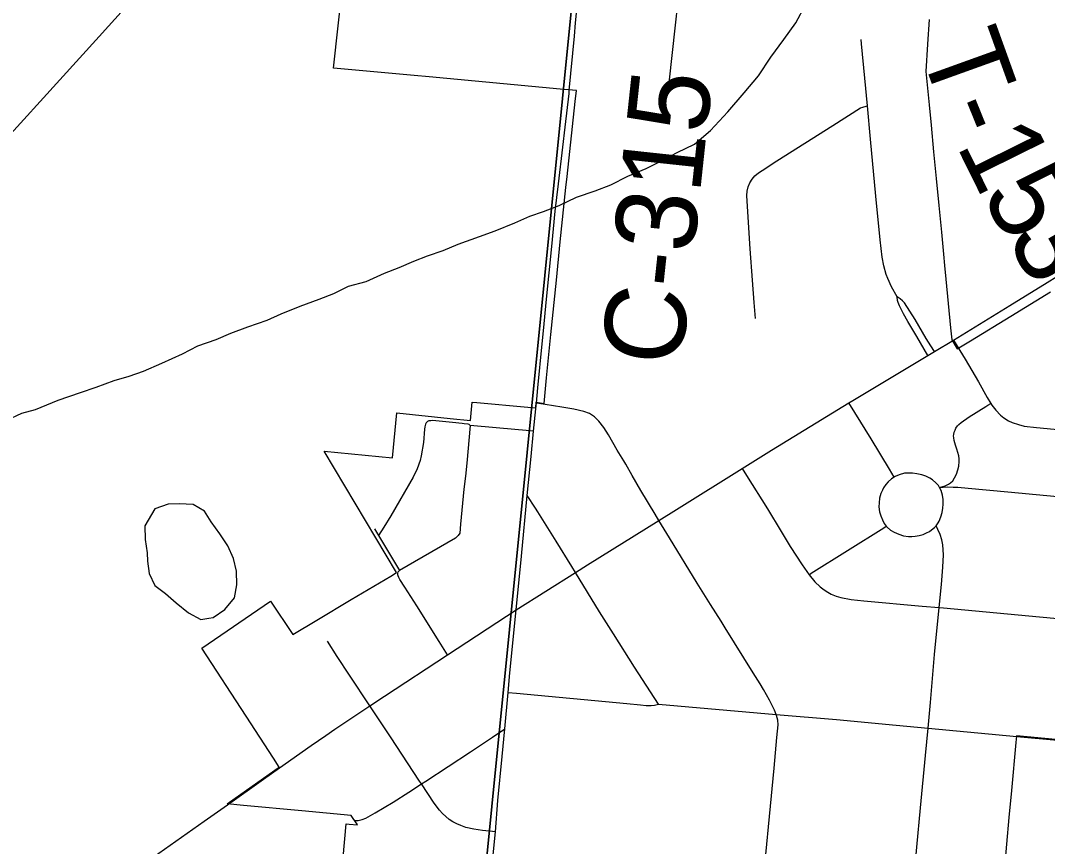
# Model space of a CAD drawing. Extents: x 0 to 1134, y 0 to 440.
# Drawn here: x 840.146 to 840.868, y 359.679 to 360.26 of the extents above; entities that cross this region are included whole.
import ezdxf

# ---------------------------------------------------------------- set-up
doc = ezdxf.new("R2010")
doc.units = 0
for name, color, linetype in [('GM_X_City_Street', 7, 'Continuous'), ('GM_X_Corporation', 7, 'Continuous'), ('GM_X_County_Road', 7, 'Continuous'), ('GM_X_County_Road_Text', 7, 'Continuous'), ('GM_X_Minor_Lake', 7, 'Continuous'), ('GM_X_Minor_River', 7, 'Continuous'), ('GM_X_Rail_Line', 7, 'Continuous'), ('GM_X_Section', 7, 'Continuous'), ('GM_X_Township_Road', 7, 'Continuous'), ('GM_X_Township_Road_Text', 7, 'Continuous')]:
    doc.layers.add(name, color=color, linetype=linetype)

msp = doc.modelspace()

# ---------------------------------------------------------------- linework, layer by layer
at = {"layer": 'GM_X_City_Street'}
for p, q in [((840.3949, 359.90277), (840.39781, 359.89807)), ((840.39781, 359.89807), (840.41256, 359.87346))]:
    msp.add_line(p, q, dxfattribs=at)
for points in [[(840.60156, 360.20947), (840.60228, 360.21871), (840.61255, 360.31077), (840.61317, 360.31691), (840.61324, 360.31949), (840.61302, 360.32134), (840.61271, 360.32289), (840.61213, 360.32471), (840.61181, 360.32541), (840.61122, 360.32624), (840.61051, 360.32689), (840.60976, 360.32745), (840.6084, 360.32821)], [(840.76245, 360.06595), (840.75853, 360.07314), (840.75583, 360.07879), (840.75474, 360.08173), (840.75308, 360.08777), (840.75197, 360.09389), (840.75048, 360.10621), (840.74758, 360.13693), (840.74385, 360.17686), (840.74161, 360.20026), (840.73973, 360.21989), (840.7375, 360.24399), (840.73726, 360.24699)], [(840.66282, 360.0507), (840.66186, 360.06191), (840.66066, 360.07778), (840.65911, 360.09976), (840.65784, 360.11837), (840.65686, 360.13721), (840.65704, 360.14031), (840.6577, 360.14333), (840.65888, 360.14621), (840.66047, 360.14887), (840.6625, 360.15121), (840.66492, 360.15317), (840.66748, 360.15493), (840.67787, 360.16175), (840.71732, 360.18655), (840.73667, 360.19893), (840.73842, 360.19949), (840.74073, 360.20005), (840.74161, 360.20026)], [(840.78871, 360.02752), (840.78623, 360.03149), (840.78299, 360.03668), (840.77504, 360.05002), (840.76754, 360.06169), (840.76635, 360.0632), (840.76468, 360.06454), (840.76245, 360.06595)], [(840.78416, 360.02479), (840.78155, 360.02928), (840.7764, 360.03811), (840.77006, 360.04855), (840.76703, 360.05394), (840.7642, 360.05967), (840.76322, 360.06194), (840.76279, 360.06349), (840.76245, 360.06595)], [(840.80205, 360.03551), (840.81037, 360.02212), (840.81962, 360.00617), (840.82571, 359.99509), (840.82833, 359.99104), (840.82911, 359.98983), (840.83177, 359.9862), (840.83515, 359.98282), (840.83758, 359.98088), (840.84084, 359.97883), (840.84326, 359.97762), (840.84773, 359.97617), (840.85184, 359.97508), (840.86042, 359.97397), (840.9175, 359.96867), (840.91973, 359.96846)], [(840.59481, 359.90874), (840.5922, 359.91315), (840.58234, 359.92978), (840.57603, 359.9403), (840.57157, 359.94817), (840.5703, 359.9506), (840.56557, 359.95812), (840.55946, 359.96892), (840.55622, 359.97414), (840.55262, 359.97863), (840.54974, 359.98151), (840.54614, 359.98385), (840.54219, 359.98529), (840.53517, 359.9869), (840.52672, 359.98835), (840.51506, 359.99028), (840.50886, 359.99129)], [(840.76049, 359.9392), (840.75707, 359.94482), (840.74413, 359.96603), (840.73268, 359.98469), (840.72858, 359.99138)], [(840.79231, 359.93183), (840.79614, 359.93304), (840.79855, 359.93415), (840.80006, 359.93526), (840.80157, 359.93667), (840.80288, 359.93871), (840.8042, 359.94136), (840.80526, 359.94427), (840.80592, 359.94691), (840.80618, 359.95008), (840.806, 359.95205), (840.80579, 359.95405), (840.80433, 359.9589), (840.80354, 359.96158), (840.803, 359.96335), (840.80248, 359.96503), (840.80223, 359.96669), (840.80218, 359.96821), (840.80229, 359.96925), (840.80265, 359.97077), (840.80318, 359.97213), (840.80385, 359.97364), (840.80495, 359.97522), (840.80592, 359.97626), (840.80746, 359.97762), (840.81316, 359.98147), (840.82482, 359.98883), (840.82628, 359.98974), (840.82833, 359.99104)], [(840.46229, 359.97558), (840.46143, 359.97618), (840.4608, 359.97641), (840.45804, 359.97671), (840.45657, 359.97687), (840.44988, 359.97755), (840.43582, 359.9789), (840.4345, 359.97886), (840.43313, 359.97869), (840.43229, 359.97831), (840.43177, 359.97787), (840.43127, 359.97734), (840.43075, 359.97644), (840.43047, 359.97552), (840.43034, 359.97443), (840.43021, 359.97281), (840.42935, 359.96342), (840.42785, 359.95404), (840.42704, 359.95094), (840.42486, 359.94494), (840.42212, 359.93921), (840.40638, 359.91196), (840.40142, 359.90392), (840.39781, 359.89807)], [(840.46229, 359.97558), (840.45986, 359.94902), (840.45885, 359.93987), (840.45788, 359.9307), (840.45543, 359.90606), (840.45495, 359.89969)], [(840.50683, 359.97149), (840.50413, 359.97175), (840.48056, 359.97394), (840.46229, 359.97558)], [(840.65338, 359.9453), (840.65647, 359.94037), (840.67123, 359.91688), (840.68082, 359.90097), (840.6873, 359.89045), (840.69569, 359.87744), (840.7005, 359.87053), (840.7045, 359.86554), (840.70831, 359.86197), (840.71105, 359.85994), (840.71367, 359.85815), (840.71605, 359.85672), (840.71968, 359.85542), (840.72296, 359.85458), (840.73011, 359.85315), (840.73905, 359.85207), (840.77997, 359.84842), (840.79202, 359.84738), (840.79507, 359.84711), (840.9327, 359.83422)], [(840.78985, 359.90496), (840.79133, 359.90706), (840.79197, 359.90807), (840.79322, 359.91122), (840.79417, 359.91429), (840.79465, 359.91725), (840.79494, 359.92022), (840.79494, 359.92347), (840.79438, 359.92646), (840.79342, 359.92982), (840.79231, 359.93183), (840.79144, 359.93327), (840.78962, 359.93519), (840.78728, 359.93715), (840.78537, 359.93839), (840.78269, 359.93974), (840.77992, 359.94069), (840.77628, 359.94155), (840.77331, 359.94194), (840.77064, 359.94203), (840.76757, 359.94184), (840.76387, 359.94089), (840.76107, 359.93959), (840.76049, 359.9392), (840.75853, 359.93785), (840.75622, 359.93582), (840.75456, 359.9339), (840.75288, 359.93154), (840.75208, 359.92997), (840.75093, 359.92768), (840.75016, 359.92443), (840.74988, 359.92118), (840.74968, 359.91821), (840.75016, 359.91486), (840.75103, 359.91199), (840.75208, 359.90921), (840.75342, 359.90644), (840.75483, 359.90462), (840.75542, 359.90386), (840.75782, 359.90185), (840.7604, 359.90041), (840.76375, 359.89897), (840.767, 359.89792), (840.77035, 359.89745), (840.77284, 359.89745), (840.77523, 359.89754), (840.77801, 359.89802), (840.78088, 359.89888), (840.78317, 359.89993), (840.78518, 359.90099), (840.78662, 359.90204), (840.78872, 359.90376), (840.78985, 359.90496)], [(840.79231, 359.93183), (840.79765, 359.93234), (840.80197, 359.93214), (840.8052, 359.93199), (840.8123, 359.93134), (840.84022, 359.92871), (840.91502, 359.92169), (841.01067, 359.91272), (841.01674, 359.91212), (841.0589, 359.908), (841.07221, 359.90664), (841.08044, 359.90589), (841.13596, 359.90053), (841.13828, 359.9003)], [(840.53625, 359.87214), (840.53377, 359.87618), (840.52273, 359.89418), (840.50982, 359.91469), (840.50819, 359.91723), (840.50237, 359.92628)], [(840.66765, 359.64703), (840.67261, 359.70051), (840.67603, 359.73451), (840.67783, 359.7561), (840.67877, 359.76497), (840.67857, 359.76824), (840.67771, 359.7714), (840.6774, 359.77217), (840.67621, 359.77517), (840.67279, 359.78218), (840.66848, 359.78974), (840.66615, 359.79364), (840.66125, 359.80157), (840.64164, 359.83325), (840.63872, 359.83786), (840.63118, 359.84961), (840.62182, 359.8646), (840.60242, 359.89641), (840.59481, 359.90874)], [(840.45495, 359.89969), (840.45381, 359.89803), (840.45183, 359.89616), (840.41256, 359.87346)], [(840.7005, 359.87053), (840.70205, 359.8715), (840.75318, 359.90359), (840.75483, 359.90462)], [(840.75627, 359.46433), (840.75647, 359.46636), (840.76335, 359.5367), (840.76408, 359.5446), (840.77149, 359.62532), (840.77375, 359.64996), (840.77643, 359.67877), (840.77886, 359.70662), (840.78238, 359.74321), (840.78427, 359.76261), (840.78599, 359.78071), (840.7888, 359.81428), (840.79202, 359.84738), (840.79358, 359.86351), (840.79461, 359.87589), (840.79499, 359.88461), (840.79465, 359.89146), (840.79396, 359.89493), (840.79265, 359.89887), (840.79105, 359.90234), (840.78985, 359.90496)], [(840.44637, 359.81411), (840.44287, 359.81966), (840.44043, 359.82352), (840.4246, 359.84863), (840.4163, 359.86171), (840.41283, 359.86719), (840.41201, 359.86866), (840.41156, 359.86966), (840.41136, 359.87041), (840.41138, 359.87148), (840.41166, 359.87242), (840.41256, 359.87346)], [(840.59465, 359.77933), (840.57775, 359.80557), (840.56299, 359.82893), (840.5531, 359.84433), (840.53625, 359.87214)], [(840.39164, 359.77826), (840.37747, 359.79977), (840.3686, 359.81303), (840.36182, 359.82385)], [(840.48893, 359.78774), (840.49487, 359.78718), (840.57246, 359.77981), (840.58211, 359.77889), (840.58602, 359.77857), (840.58939, 359.77857), (840.5919, 359.77879), (840.59465, 359.77933)], [(840.47995, 359.68961), (840.47783, 359.68983), (840.47099, 359.69052), (840.46475, 359.69149), (840.45917, 359.69268), (840.45561, 359.69401), (840.45275, 359.69523), (840.45001, 359.69669), (840.44742, 359.69842), (840.44501, 359.70037), (840.44277, 359.70253), (840.44071, 359.70486), (840.43698, 359.70982), (840.42788, 359.72333), (840.42656, 359.72528), (840.40617, 359.75651), (840.39164, 359.77826)], [(840.59465, 359.77933), (840.6774, 359.77217), (840.71984, 359.76854), (840.76173, 359.76472), (840.78427, 359.76261), (840.8466, 359.75666)], [(840.38073, 359.69758), (840.38351, 359.6977), (840.38618, 359.69828), (840.38874, 359.69921), (840.39535, 359.70304), (840.408, 359.71058), (840.41903, 359.71743), (840.42788, 359.72333), (840.43095, 359.72538), (840.46244, 359.74587), (840.47785, 359.75618), (840.48652, 359.76198)]]:
    msp.add_lwpolyline(points, dxfattribs=at)
at = {"layer": 'GM_X_Corporation'}
for points in [[(840.37286, 359.67168), (840.37499, 359.69518), (840.37709, 359.695), (840.38301, 359.69447), (840.38264, 359.69503), (840.38003, 359.69898), (840.37854, 359.70123), (840.34377, 359.70445), (840.30288, 359.70823), (840.29132, 359.70932), (840.32491, 359.73297), (840.32802, 359.73516), (840.32398, 359.74136), (840.30464, 359.77103), (840.27349, 359.81882), (840.32188, 359.85185), (840.33756, 359.82845), (840.35442, 359.83852), (840.37858, 359.85296), (840.40632, 359.86953), (840.41036, 359.87212), (840.35966, 359.95745), (840.40759, 359.95279), (840.41073, 359.98431), (840.4481, 359.9804), (840.46253, 359.9789), (840.46372, 359.99187), (840.46683, 359.99159), (840.50266, 359.98832), (840.50832, 359.9878), (840.50869, 359.99189), (840.51418, 359.99102), (840.51596, 360.00891), (840.51901, 360.03948), (840.52282, 360.07782), (840.52551, 360.10479), (840.52949, 360.14281), (840.53035, 360.1507), (840.53608, 360.20351), (840.53691, 360.21115), (840.52559, 360.21219), (840.43335, 360.22068), (840.42279, 360.22165), (840.36621, 360.22686), (840.37846, 360.33985)], [(840.78497, 360.26113), (840.78389, 360.24369), (840.7827, 360.22455), (840.78452, 360.2057), (840.78495, 360.20117), (840.78633, 360.18685), (840.78814, 360.168), (840.78995, 360.14914), (840.79176, 360.13029), (840.79358, 360.11144), (840.79506, 360.09597), (840.79582, 360.08804), (840.79675, 360.07844), (840.80003, 360.04422), (840.80083, 360.03584), (840.80479, 360.02937), (840.81399, 360.035), (840.84233, 360.05233), (840.8704, 360.06951)], [(841.00083, 359.74258), (840.84637, 359.75719), (840.84588, 359.75257), (840.84281, 359.71866), (840.84111, 359.6998), (840.8394, 359.68093), (840.8377, 359.66207)]]:
    msp.add_lwpolyline(points, dxfattribs=at)
at = {"layer": 'GM_X_County_Road'}
for p, q in [((840.78871, 360.02752), (840.80205, 360.03551)), ((840.78416, 360.02479), (840.78871, 360.02752)), ((840.50864, 359.98927), (840.50886, 359.99129)), ((840.49456, 359.84569), (840.53625, 359.87214)), ((840.44637, 359.81411), (840.49456, 359.84569)), ((840.48652, 359.76198), (840.48893, 359.78774))]:
    msp.add_line(p, q, dxfattribs=at)
for points in [[(840.53173, 360.20908), (840.53194, 360.21106), (840.53547, 360.24933), (840.53636, 360.25887), (840.53801, 360.27469), (840.53926, 360.28695), (840.54137, 360.30753)], [(840.52743, 360.17132), (840.52912, 360.18528), (840.53173, 360.20908)], [(840.51375, 360.04203), (840.51586, 360.06426), (840.51961, 360.10142), (840.5221, 360.12624), (840.52431, 360.14539), (840.52743, 360.17132)], [(840.80205, 360.03551), (840.84166, 360.06), (840.86793, 360.07611), (840.87473, 360.08032)], [(840.50886, 359.99129), (840.5098, 360.00205), (840.51289, 360.03294), (840.51375, 360.04203)], [(840.72858, 359.99138), (840.7313, 359.99304), (840.78416, 360.02479)], [(840.50683, 359.97149), (840.50843, 359.98725), (840.50864, 359.98927)], [(840.65338, 359.9453), (840.67401, 359.95813), (840.72858, 359.99138)], [(840.50237, 359.92628), (840.50502, 359.95376), (840.50683, 359.97149)], [(840.59481, 359.90874), (840.60722, 359.91643), (840.65338, 359.9453)], [(840.49456, 359.84569), (840.49823, 359.88349), (840.50237, 359.92628)], [(840.53625, 359.87214), (840.54477, 359.87755), (840.59481, 359.90874)], [(840.48893, 359.78774), (840.49022, 359.80154), (840.49456, 359.84569)], [(840.39164, 359.77826), (840.40194, 359.785), (840.44637, 359.81411)], [(840.36078, 359.75751), (840.36712, 359.76192), (840.39164, 359.77826)], [(840.47995, 359.68961), (840.48178, 359.71156), (840.48473, 359.74273), (840.48652, 359.76198)], [(840.31685, 359.72666), (840.32094, 359.72958), (840.32813, 359.7346), (840.35048, 359.75034), (840.36078, 359.75751)], [(840.27515, 359.69707), (840.29148, 359.70854), (840.31685, 359.72666)], [(840.21789, 359.65667), (840.24329, 359.67469), (840.27515, 359.69707)], [(840.4764, 359.65182), (840.4792, 359.68049), (840.47995, 359.68961)]]:
    msp.add_lwpolyline(points, dxfattribs=at)
at = {"layer": 'GM_X_Minor_Lake'}
for points in [[(840.24036, 359.91689), (840.23337, 359.90483), (840.23364, 359.89533), (840.23504, 359.88582), (840.23535, 359.88012), (840.23638, 359.87138), (840.24046, 359.86297), (840.24798, 359.85719), (840.2555, 359.85064), (840.26415, 359.8437), (840.27283, 359.83903), (840.27834, 359.83992)], [(840.27834, 359.83992), (840.28158, 359.84044), (840.28963, 359.84604), (840.29657, 359.8543), (840.2982, 359.8634), (840.29794, 359.87289), (840.29577, 359.88203), (840.2917, 359.89081), (840.28611, 359.89923), (840.28013, 359.90766), (840.27529, 359.91532), (840.26737, 359.91997), (840.2575, 359.92047), (840.2499, 359.92019), (840.24036, 359.91689)]]:
    msp.add_lwpolyline(points, dxfattribs=at)
at = {"layer": 'GM_X_Minor_River'}
msp.add_lwpolyline([(840.13589, 359.97892), (840.14697, 359.9841), (840.1565, 359.98664), (840.17254, 359.99328), (840.18818, 359.99878), (840.19925, 360.00244), (840.21184, 360.00722), (840.22251, 360.01013), (840.23244, 360.0138), (840.24542, 360.01933), (840.25994, 360.02599), (840.27064, 360.03155), (840.28361, 360.03595), (840.29393, 360.04037), (840.30576, 360.04478), (840.31949, 360.04955), (840.32942, 360.05398), (840.34279, 360.05951), (840.35614, 360.06428), (840.36645, 360.06833), (840.37677, 360.07351), (840.38897, 360.07678), (840.40196, 360.08269), (840.41226, 360.08674), (840.42257, 360.09117), (840.43212, 360.09485), (840.44318, 360.09851), (840.45387, 360.10293), (840.46875, 360.10844), (840.47982, 360.11248), (840.49357, 360.118), (840.50426, 360.12281), (840.5138, 360.1261), (840.52486, 360.13014), (840.5371, 360.13607), (840.55007, 360.14046), (840.56114, 360.14488), (840.57299, 360.15081), (840.58597, 360.15634), (840.59591, 360.16115), (840.60776, 360.16746), (840.61999, 360.17338), (840.63113, 360.18311), (840.64345, 360.19625), (840.655, 360.2094), (840.66503, 360.22142), (840.67355, 360.23461), (840.68282, 360.24702), (840.69132, 360.25868), (840.69794, 360.27151)], dxfattribs=at)
at = {"layer": 'GM_X_Rail_Line'}
msp.add_lwpolyline([(839.12381, 359.05896), (839.46789, 359.43891), (839.4972, 359.47117), (839.65928, 359.64982), (839.88775, 359.90268), (839.94474, 359.9674), (839.97309, 359.99685), (840.01432, 360.04279), (840.10674, 360.14505), (840.20123, 360.24917), (840.26303, 360.31763), (840.32373, 360.38445), (840.34221, 360.4037), (840.38104, 360.44176), (840.40717, 360.46768), (840.45005, 360.50082), (840.47594, 360.52056), (840.51734, 360.54982), (840.57746, 360.59086), (840.60634, 360.61131)], dxfattribs=at)
at = {"layer": 'GM_X_Section'}
for points in [[(839.54401, 360.57395), (840.55206, 360.45491), (840.45254, 359.45844), (839.46986, 359.55389), (839.44869, 359.55612)], [(840.55206, 360.45491), (841.56432, 360.36118), (841.46281, 359.35837), (840.47447, 359.45619), (840.45254, 359.45844)]]:
    msp.add_lwpolyline(points, close=True, dxfattribs=at)
at = {"layer": 'GM_X_Township_Road'}
msp.add_lwpolyline([(840.8466, 359.75666), (840.87514, 359.75403), (840.89987, 359.75164), (840.93887, 359.74793), (841.00132, 359.7422)], dxfattribs=at)

# ---------------------------------------------------------------- texts
at = {"layer": 'GM_X_County_Road_Text'}
msp.add_text('C-315', height=0.056818, rotation=83.87478, dxfattribs=at).set_placement((840.6107, 360.0161))
at = {"layer": 'GM_X_Township_Road_Text'}
for s, rotation, p in [('T', 289.81945, (840.7778, 360.24089)), ('-', 292.05611, (840.79308, 360.19865)), ('1', 296.31147, (840.80372, 360.17283)), ('5', 299.81986, (840.82102, 360.13811)), ('3', 300.27638, (840.83867, 360.10731))]:
    msp.add_text(s, height=0.05682, rotation=rotation, dxfattribs=at).set_placement(p)

doc.saveas('drawing.dxf')
